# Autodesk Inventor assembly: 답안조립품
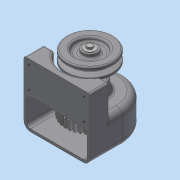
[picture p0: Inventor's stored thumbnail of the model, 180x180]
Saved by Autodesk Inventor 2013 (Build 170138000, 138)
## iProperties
Created: 2015-02
Part Number: 답안조립품
Document SubType Name: Assembly
Designer: Administrator
Author: Administrator
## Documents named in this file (14)
- C:\Documents and Settings\Administrator\바탕 화면\450214V1010\답안조립품.iam
- C:\Documents and Settings\Administrator\바탕 화면\450214V1010\1-본체.ipt
- C:\Documents and Settings\Administrator\바탕 화면\450214V1010\베어링 6001.ipt
- C:\Documents and Settings\Administrator\바탕 화면\450214V1010\축.ipt
- C:\Documents and Settings\Administrator\바탕 화면\450214V1010\키5x5.ipt
- C:\Documents and Settings\Administrator\바탕 화면\450214V1010\스퍼기어.ipt
- C:\Documents and Settings\Administrator\바탕 화면\450214V1010\축커버.ipt
- C:\Documents and Settings\Administrator\바탕 화면\450214V1010\오일실.ipt
- C:\Documents and Settings\Administrator\바탕 화면\450214V1010\M3x0.5.ipt
- C:\Documents and Settings\Administrator\바탕 화면\450214V1010\키4x4.ipt
- C:\Documents and Settings\Administrator\바탕 화면\450214V1010\4-V-벨트풀리.ipt
- C:\Documents and Settings\Administrator\바탕 화면\450214V1010\와샤.ipt
- C:\Documents and Settings\Administrator\바탕 화면\450214V1010\M5x0.8.ipt
- M5x0.8.ipt
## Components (7 placed, 4 different names)
1. 1-본체:1
2. 4-V-벨트풀리:1 — 각도:4
3. M5x0.8:1 — 각도:5
4. M3x0.5:1
5. M3x0.5:2
6. M3x0.5:3
7. M3x0.5:4
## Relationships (2: Angle 2)
- 각도:4 [Angle]: 4-V-벨트풀리:1
- 각도:5 [Angle]: M5x0.8:1
